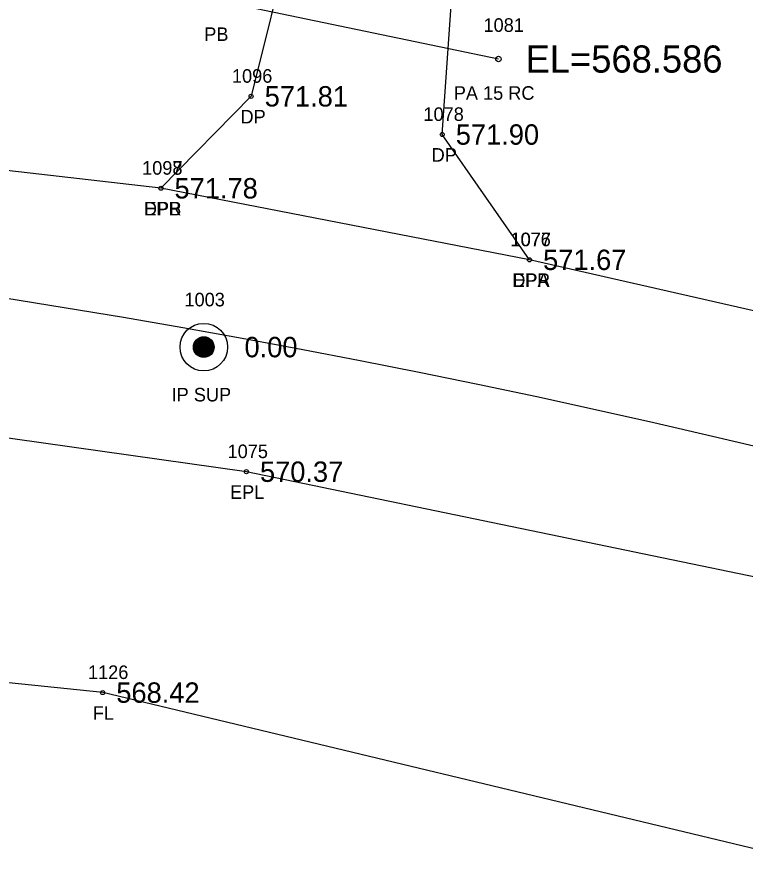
# Model space of a CAD drawing. Extents: x 1529475 to 1532053, y 876698 to 877911.
# Drawn here: x 1531265.9 to 1531319.5, y 877232.8 to 877295.3 of the extents above; entities that cross this region are included whole.
import ezdxf

# ---------------------------------------------------------------- set-up
doc = ezdxf.new("R2010")
doc.units = 0
for name, color, linetype in [('RD_EX_DR_Pipe', 7, 'Continuous'), ('RD_EX_DR_Pipe_txCode', 7, 'Continuous'), ('RD_EX_Driveway', 7, 'Continuous'), ('RD_EX_Driveway_txCode', 7, 'Continuous'), ('RD_EX_DV_Prop_txCode', 7, 'Continuous'), ('RD_EX_DV_PropPin', 7, 'Continuous'), ('RD_EX_Fence_Other', 7, 'Continuous'), ('RD_EX_Fence_Other_txCode', 7, 'Continuous'), ('RD_EX_Road', 7, 'Continuous'), ('RD_EX_Road_txCode', 7, 'Continuous'), ('RD_EX_TX_Driveway_ELEV', 7, 'Continuous'), ('RD_EX_TX_DV_Prop_ELEV', 7, 'Continuous'), ('RD_EX_TX_Fence_Other_ELEV', 7, 'Continuous'), ('RD_EX_TX_Road_ELEV', 7, 'Continuous'), ('RD_HC_Cl', 7, 'Continuous'), ('RD_SMD_Locator', 7, 'Continuous'), ('RD_TX_Pipe_ElevEX', 7, 'Continuous')]:
    doc.layers.add(name, color=color, linetype=linetype)

msp = doc.modelspace()

# ---------------------------------------------------------------- linework, layer by layer
at = {"layer": 'RD_EX_DR_Pipe'}
msp.add_line((1531301.38, 877292.224), (1531280.491, 877296.553), dxfattribs=at)
at = {"layer": 'RD_EX_Driveway'}
msp.add_lwpolyline([(1531303.666, 877277.444), (1531297.238, 877286.667), (1531298.088, 877298.975), (1531286.084, 877301.254), (1531283.161, 877289.479), (1531276.518, 877282.709)], dxfattribs=at)
at = {"layer": 'RD_EX_DV_PropPin'}
for p, q in [((1531279.326, 877270.342), (1531279.326, 877271.693)), ((1531279.361, 877270.325), (1531279.361, 877271.71)), ((1531279.396, 877270.31), (1531279.396, 877271.725)), ((1531279.431, 877270.297), (1531279.431, 877271.738)), ((1531279.466, 877270.286), (1531279.466, 877271.749)), ((1531279.501, 877270.277), (1531279.501, 877271.758)), ((1531279.536, 877270.27), (1531279.536, 877271.766)), ((1531279.571, 877270.264), (1531279.571, 877271.771)), ((1531279.606, 877270.26), (1531279.606, 877271.775)), ((1531279.641, 877270.257), (1531279.641, 877271.778)), ((1531279.676, 877270.257), (1531279.676, 877271.779)), ((1531279.711, 877270.257), (1531279.711, 877271.778)), ((1531279.746, 877270.26), (1531279.746, 877271.775)), ((1531279.781, 877270.264), (1531279.781, 877271.771)), ((1531279.816, 877270.27), (1531279.816, 877271.766)), ((1531279.851, 877270.277), (1531279.851, 877271.758)), ((1531279.886, 877270.286), (1531279.886, 877271.749)), ((1531279.921, 877270.297), (1531279.921, 877271.738)), ((1531279.956, 877270.31), (1531279.956, 877271.725)), ((1531279.991, 877270.325), (1531279.991, 877271.71)), ((1531280.026, 877270.342), (1531280.026, 877271.693)), ((1531278.94, 877270.822), (1531278.94, 877271.214)), ((1531278.975, 877270.72), (1531278.975, 877271.316)), ((1531279.011, 877270.648), (1531279.011, 877271.387)), ((1531279.046, 877270.591), (1531279.046, 877271.444)), ((1531279.081, 877270.544), (1531279.081, 877271.492)), ((1531279.116, 877270.503), (1531279.116, 877271.533)), ((1531279.151, 877270.467), (1531279.151, 877271.568)), ((1531279.186, 877270.436), (1531279.186, 877271.6)), ((1531279.221, 877270.408), (1531279.221, 877271.628)), ((1531279.256, 877270.383), (1531279.256, 877271.652)), ((1531279.291, 877270.361), (1531279.291, 877271.674)), ((1531280.061, 877270.361), (1531280.061, 877271.674)), ((1531280.096, 877270.383), (1531280.096, 877271.652)), ((1531280.131, 877270.408), (1531280.131, 877271.628)), ((1531280.166, 877270.436), (1531280.166, 877271.6)), ((1531280.201, 877270.467), (1531280.201, 877271.568)), ((1531280.236, 877270.503), (1531280.236, 877271.533)), ((1531280.271, 877270.544), (1531280.271, 877271.492)), ((1531280.306, 877270.591), (1531280.306, 877271.444)), ((1531280.341, 877270.648), (1531280.341, 877271.387)), ((1531280.376, 877270.72), (1531280.376, 877271.316)), ((1531280.411, 877270.822), (1531280.411, 877271.214))]:
    msp.add_line(p, q, dxfattribs=at)
for radius in [1.75, 0.761]:
    msp.add_circle((1531279.676, 877271.018), radius, dxfattribs=at)
at = {"layer": 'RD_EX_Fence_Other'}
msp.add_lwpolyline([(1531584.499, 877106.777), (1531547.822, 877137.371), (1531457.577, 877185.314), (1531406.019, 877209.641), (1531373.66, 877220.154), (1531357.948, 877224.144), (1531321.759, 877233.707), (1531272.233, 877245.587), (1531232.596, 877249.659), (1531180.727, 877254.109), (1531131.266, 877254.15), (1531075.59, 877251.89), (1531032.65, 877249.495), (1530920.264, 877239.274), (1530908.152, 877238.577)], dxfattribs=at)
at = {"layer": 'RD_EX_Road'}
for points in [[(1531606.641, 877133.837), (1531579.15, 877155.048), (1531564.866, 877165.268), (1531535.216, 877186.029), (1531511.532, 877200.27), (1531474.57, 877218.901), (1531430.451, 877239.347), (1531404.48, 877249.379), (1531382.323, 877256.431), (1531333.233, 877270.709), (1531303.666, 877277.444), (1531276.518, 877282.709), (1531237.324, 877287.202), (1531185.802, 877290.94), (1531132.609, 877292.767), (1531081.114, 877292.384), (1531038.69, 877288.667), (1530976.423, 877285.451), (1530941.057, 877284.256)], [(1531595.271, 877120.27), (1531553.556, 877149.901), (1531509.973, 877177.566), (1531465.943, 877201.729), (1531423.649, 877222.003), (1531376.086, 877237.675), (1531328.838, 877252.315), (1531282.814, 877261.847), (1531235.696, 877268.487), (1531185.47, 877272.841), (1531132.719, 877273.116), (1531080.205, 877271.871), (1531029.21, 877269.53), (1530978.473, 877268.316), (1530945.946, 877265.926), (1530941.447, 877262.437)]]:
    msp.add_lwpolyline(points, dxfattribs=at)
at = {"layer": 'RD_HC_Cl'}
msp.add_arc((1531152.265, 876558.444), 725, 47.423695, 92.332071, dxfattribs=at)
at = {"layer": 'RD_SMD_Locator'}
for centre, radius in [((1531301.38, 877292.224), 0.2), ((1531283.161, 877289.479), 0.15), ((1531297.238, 877286.667), 0.15), ((1531276.518, 877282.709), 0.15), ((1531276.518, 877282.709), 0.15), ((1531303.666, 877277.444), 0.15), ((1531303.666, 877277.444), 0.15), ((1531279.676, 877271.018), 0.15), ((1531282.814, 877261.847), 0.15), ((1531272.233, 877245.587), 0.15)]:
    msp.add_circle(centre, radius, dxfattribs=at)

# ---------------------------------------------------------------- texts
at = {"layer": 'RD_EX_DR_Pipe_txCode'}
for s, p in [('1081', (1531300.277, 877294.224)), ('PB', (1531279.711, 877293.553)), ('PA 15 RC', (1531298.088, 877289.224))]:
    msp.add_text(s, height=1, dxfattribs=at).set_placement(p)
at = {"layer": 'RD_EX_Driveway_txCode'}
for s, p in [('1096', (1531281.751, 877290.479)), ('1078', (1531295.853, 877287.667)), ('DP', (1531282.381, 877287.479)), ('DP', (1531296.459, 877284.667)), ('1097', (1531275.132, 877283.709)), ('DPB', (1531275.266, 877280.709)), ('1077', (1531302.28, 877278.444)), ('DPA', (1531302.399, 877275.444))]:
    msp.add_text(s, height=1, dxfattribs=at).set_placement(p)
at = {"layer": 'RD_EX_DV_Prop_txCode'}
for s, p in [('1003', (1531278.251, 877274.018)), ('IP SUP', (1531277.306, 877267.018))]:
    msp.add_text(s, height=1, dxfattribs=at).set_placement(p)
at = {"layer": 'RD_EX_Fence_Other_txCode'}
for s, p in [('1126', (1531271.146, 877246.587)), ('FL', (1531271.501, 877243.587))]:
    msp.add_text(s, height=1, dxfattribs=at).set_placement(p)
at = {"layer": 'RD_EX_Road_txCode'}
for s, p in [('1098', (1531275.132, 877283.709)), ('EPR', (1531275.289, 877280.709)), ('1076', (1531302.257, 877278.444)), ('EPR', (1531302.438, 877275.444)), ('1075', (1531281.428, 877262.847)), ('EPL', (1531281.609, 877259.847))]:
    msp.add_text(s, height=1, dxfattribs=at).set_placement(p)
at = {"layer": 'RD_EX_TX_Driveway_ELEV'}
for s, p in [('571.81', (1531284.161, 877288.729)), ('571.90', (1531298.238, 877285.917)), ('571.78', (1531277.518, 877281.959)), ('571.67', (1531304.666, 877276.694))]:
    msp.add_text(s, height=1.5, dxfattribs=at).set_placement(p)
at = {"layer": 'RD_EX_TX_DV_Prop_ELEV'}
msp.add_text('0.00', height=1.5, dxfattribs=at).set_placement((1531282.676, 877270.268))
at = {"layer": 'RD_EX_TX_Fence_Other_ELEV'}
msp.add_text('568.42', height=1.5, dxfattribs=at).set_placement((1531273.233, 877244.837))
at = {"layer": 'RD_EX_TX_Road_ELEV'}
for s, p in [('571.78', (1531277.518, 877281.959)), ('571.67', (1531304.666, 877276.694)), ('570.37', (1531283.814, 877261.097))]:
    msp.add_text(s, height=1.5, dxfattribs=at).set_placement(p)
at = {"layer": 'RD_TX_Pipe_ElevEX'}
msp.add_text('EL=568.586', height=2, dxfattribs=at).set_placement((1531303.38, 877291.224))

doc.saveas('drawing.dxf')
